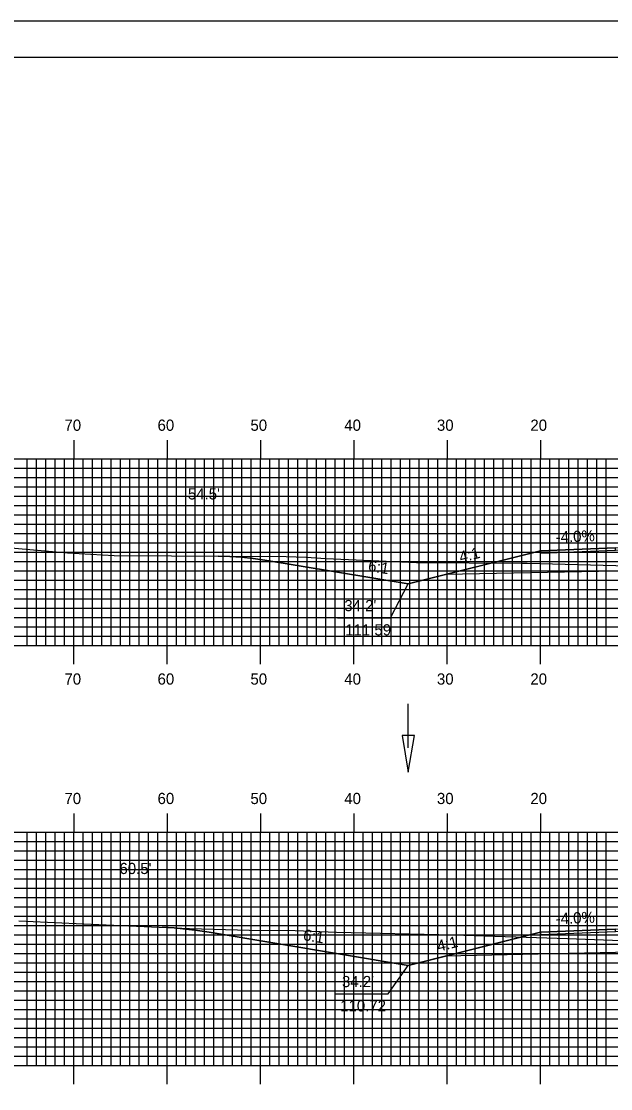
# Model space of a CAD drawing. Extents: x 1779893 to 1780236, y 442591 to 442811.
# Drawn here: x 1779982.7 to 1780045.9, y 442696.2 to 442810.5 of the extents above; entities that cross this region are included whole.
import ezdxf

# ---------------------------------------------------------------- set-up
doc = ezdxf.new("R2010")
doc.units = 0
for name, color, linetype in [('ANNOTATION', 7, 'Continuous'), ('BORDER', 7, 'Continuous'), ('D_Drainage_Ditch_Line', 7, 'Continuous'), ('D_Roadway_Centerline', 7, 'Continuous'), ('D_Roadway_Edge_Shoulder', 7, 'Continuous'), ('D_Roadway_SlopeLines', 7, 'Continuous'), ('D_Roadway_SubGrade', 7, 'Continuous'), ('D_Text_Standard', 7, 'Continuous'), ('H_V ANNOTATION', 7, 'Continuous'), ('MAJOR', 7, 'Continuous'), ('MINOR', 7, 'Continuous'), ('PLOT BOUNDARY', 7, 'Continuous'), ('S_Roadway_Centerline', 7, 'Continuous')]:
    doc.layers.add(name, color=color, linetype=linetype)

msp = doc.modelspace()

# ---------------------------------------------------------------- linework, layer by layer
at = {"layer": 'ANNOTATION'}
for points in [[(1780016.6, 442746.61), (1780022.29, 442746.61), (1780024.18, 442750.26)], [(1780016.34, 442706.32), (1780022.04, 442706.32), (1780024.18, 442709.38)]]:
    msp.add_lwpolyline(points, dxfattribs=at)
at = {"layer": 'BORDER'}
msp.add_lwpolyline([(1779908.76, 442596.67), (1780228.76, 442596.67), (1780228.76, 442806.67), (1779908.76, 442806.67)], close=True, dxfattribs=at)
at = {"layer": 'D_Drainage_Ditch_Line'}
msp.add_line((1780024.18, 442732.71), (1780024.18, 442737.41), dxfattribs=at)
msp.add_lwpolyline([(1780024.84, 442734.02), (1780023.53, 442734.02), (1780024.18, 442730.09)], close=True, dxfattribs=at)
at = {"layer": 'D_Roadway_Centerline'}
for points in [[(1780003.83, 442753.25), (1780005.08, 442753.21), (1780006.33, 442753.13), (1780007.58, 442753), (1780008.83, 442752.82), (1780024.18, 442750.26), (1780028.18, 442751.26), (1780038.36, 442753.8), (1780046.36, 442754.12), (1780058.36, 442754.36), (1780070.36, 442754.12), (1780078.36, 442753.8), (1780088.53, 442751.26), (1780092.53, 442750.26), (1780093.73, 442750.43), (1780094.94, 442750.53), (1780096.14, 442750.58), (1780097.34, 442750.56)], [(1779997.87, 442713.47), (1779999.12, 442713.39), (1780000.37, 442713.28), (1780001.62, 442713.12), (1780002.87, 442712.94), (1780024.18, 442709.38), (1780028.18, 442710.38), (1780038.36, 442712.93), (1780046.36, 442713.25), (1780058.36, 442713.49), (1780070.36, 442713.25), (1780078.36, 442712.93), (1780088.53, 442710.38), (1780092.53, 442709.38), (1780095.2, 442709.83), (1780096.45, 442710), (1780097.7, 442710.11), (1780098.95, 442710.16), (1780100.2, 442710.13)]]:
    msp.add_lwpolyline(points, dxfattribs=at)
at = {"layer": 'D_Roadway_Edge_Shoulder'}
for points in [[(1780046.36, 442754.12), (1780038.36, 442753.8), (1780038.36, 442753.55), (1780046.36, 442753.87)], [(1780046.36, 442713.25), (1780038.36, 442712.93), (1780038.36, 442712.68), (1780046.36, 442713)]]:
    msp.add_lwpolyline(points, close=True, dxfattribs=at)
at = {"layer": 'D_Roadway_SlopeLines'}
for points in [[(1780024.18, 442750.26), (1780008.83, 442752.82), (1780007.58, 442753), (1780006.33, 442753.13), (1780005.08, 442753.21), (1780003.83, 442753.25)], [(1780038.36, 442753.8), (1780024.18, 442750.26)], [(1780024.18, 442709.38), (1780002.87, 442712.94), (1780001.62, 442713.12), (1780000.37, 442713.28), (1779999.12, 442713.39), (1779997.87, 442713.47)], [(1780038.36, 442712.93), (1780024.18, 442709.38)]]:
    msp.add_lwpolyline(points, dxfattribs=at)
at = {"layer": 'D_Roadway_SubGrade'}
for points in [[(1780046.36, 442751.62), (1780028.18, 442751.26), (1780038.36, 442753.8), (1780038.36, 442753.55), (1780046.36, 442753.87), (1780058.36, 442754.11), (1780070.36, 442753.87), (1780078.36, 442753.55), (1780078.36, 442753.8), (1780088.53, 442751.26), (1780070.36, 442751.62), (1780058.36, 442751.86)], [(1780046.36, 442710.75), (1780028.18, 442710.38), (1780038.36, 442712.93), (1780038.36, 442712.68), (1780046.36, 442713), (1780058.36, 442713.24), (1780070.36, 442713), (1780078.36, 442712.68), (1780078.36, 442712.93), (1780088.53, 442710.38), (1780070.36, 442710.75), (1780058.36, 442710.99)]]:
    msp.add_lwpolyline(points, close=True, dxfattribs=at)
at = {"layer": 'MAJOR'}
for p, q in [((1779988.36, 442765.67), (1779988.36, 442763.67)), ((1779998.36, 442765.67), (1779998.36, 442763.67)), ((1780008.36, 442765.67), (1780008.36, 442763.67)), ((1780018.36, 442765.67), (1780018.36, 442763.67)), ((1780028.36, 442765.67), (1780028.36, 442763.67)), ((1780038.36, 442765.67), (1780038.36, 442763.67)), ((1779918.36, 442763.67), (1780198.36, 442763.67)), ((1779918.36, 442763.67), (1780198.36, 442763.67)), ((1779988.36, 442743.67), (1779988.36, 442763.67)), ((1779998.36, 442743.67), (1779998.36, 442763.67)), ((1780008.36, 442743.67), (1780008.36, 442763.67)), ((1780018.36, 442743.67), (1780018.36, 442763.67)), ((1780028.36, 442743.67), (1780028.36, 442763.67)), ((1780038.36, 442743.67), (1780038.36, 442763.67)), ((1779918.36, 442758.67), (1780198.36, 442758.67)), ((1779918.36, 442753.67), (1780198.36, 442753.67)), ((1779918.36, 442748.67), (1780198.36, 442748.67)), ((1779918.36, 442743.67), (1780198.36, 442743.67)), ((1779918.36, 442743.67), (1780198.36, 442743.67)), ((1779988.36, 442741.66), (1779988.36, 442743.67)), ((1779998.36, 442741.66), (1779998.36, 442743.67)), ((1780008.36, 442741.66), (1780008.36, 442743.67)), ((1780018.36, 442741.66), (1780018.36, 442743.67)), ((1780028.36, 442741.66), (1780028.36, 442743.67)), ((1780038.36, 442741.66), (1780038.36, 442743.67)), ((1779988.36, 442725.67), (1779988.36, 442723.67)), ((1779998.36, 442725.67), (1779998.36, 442723.67)), ((1780008.36, 442725.67), (1780008.36, 442723.67)), ((1780018.36, 442725.67), (1780018.36, 442723.67)), ((1780028.36, 442725.67), (1780028.36, 442723.67)), ((1780038.36, 442725.67), (1780038.36, 442723.67)), ((1779918.36, 442723.67), (1780198.36, 442723.67)), ((1779918.36, 442723.67), (1780198.36, 442723.67)), ((1779988.36, 442698.67), (1779988.36, 442723.67)), ((1779998.36, 442698.67), (1779998.36, 442723.67)), ((1780008.36, 442698.67), (1780008.36, 442723.67)), ((1780018.36, 442698.67), (1780018.36, 442723.67)), ((1780028.36, 442698.67), (1780028.36, 442723.67)), ((1780038.36, 442698.67), (1780038.36, 442723.67)), ((1779918.36, 442718.67), (1780198.36, 442718.67)), ((1779918.36, 442713.67), (1780198.36, 442713.67)), ((1779918.36, 442708.67), (1780198.36, 442708.67)), ((1779918.36, 442703.67), (1780198.36, 442703.67)), ((1779918.36, 442698.67), (1780198.36, 442698.67)), ((1779918.36, 442698.67), (1780198.36, 442698.67)), ((1779988.36, 442696.66), (1779988.36, 442698.67)), ((1779998.36, 442696.66), (1779998.36, 442698.67)), ((1780008.36, 442696.66), (1780008.36, 442698.67)), ((1780018.36, 442696.66), (1780018.36, 442698.67)), ((1780028.36, 442696.66), (1780028.36, 442698.67)), ((1780038.36, 442696.66), (1780038.36, 442698.67))]:
    msp.add_line(p, q, dxfattribs=at)
at = {"layer": 'MINOR'}
for p, q in [((1779983.36, 442743.67), (1779983.36, 442763.67)), ((1779984.36, 442743.67), (1779984.36, 442763.67)), ((1779985.36, 442743.67), (1779985.36, 442763.67)), ((1779986.36, 442743.67), (1779986.36, 442763.67)), ((1779987.36, 442743.67), (1779987.36, 442763.67)), ((1779989.36, 442743.67), (1779989.36, 442763.67)), ((1779990.36, 442743.67), (1779990.36, 442763.67)), ((1779991.36, 442743.67), (1779991.36, 442763.67)), ((1779992.36, 442743.67), (1779992.36, 442763.67)), ((1779993.36, 442743.67), (1779993.36, 442763.67)), ((1779994.36, 442743.67), (1779994.36, 442763.67)), ((1779995.36, 442743.67), (1779995.36, 442763.67)), ((1779996.36, 442743.67), (1779996.36, 442763.67)), ((1779997.36, 442743.67), (1779997.36, 442763.67)), ((1779999.36, 442743.67), (1779999.36, 442763.67)), ((1780000.36, 442743.67), (1780000.36, 442763.67)), ((1780001.36, 442743.67), (1780001.36, 442763.67)), ((1780002.36, 442743.67), (1780002.36, 442763.67)), ((1780003.36, 442743.67), (1780003.36, 442763.67)), ((1780004.36, 442743.67), (1780004.36, 442763.67)), ((1780005.36, 442743.67), (1780005.36, 442763.67)), ((1780006.36, 442743.67), (1780006.36, 442763.67)), ((1780007.36, 442743.67), (1780007.36, 442763.67)), ((1780009.36, 442743.67), (1780009.36, 442763.67)), ((1780010.36, 442743.67), (1780010.36, 442763.67)), ((1780011.36, 442743.67), (1780011.36, 442763.67)), ((1780012.36, 442743.67), (1780012.36, 442763.67)), ((1780013.36, 442743.67), (1780013.36, 442763.67)), ((1780014.36, 442743.67), (1780014.36, 442763.67)), ((1780015.36, 442743.67), (1780015.36, 442763.67)), ((1780016.36, 442743.67), (1780016.36, 442763.67)), ((1780017.36, 442743.67), (1780017.36, 442763.67)), ((1780019.36, 442743.67), (1780019.36, 442763.67)), ((1780020.36, 442743.67), (1780020.36, 442763.67)), ((1780021.36, 442743.67), (1780021.36, 442763.67)), ((1780022.36, 442743.67), (1780022.36, 442763.67)), ((1780023.36, 442743.67), (1780023.36, 442763.67)), ((1780024.36, 442743.67), (1780024.36, 442763.67)), ((1780025.36, 442743.67), (1780025.36, 442763.67)), ((1780026.36, 442743.67), (1780026.36, 442763.67)), ((1780027.36, 442743.67), (1780027.36, 442763.67)), ((1780029.36, 442743.67), (1780029.36, 442763.67)), ((1780030.36, 442743.67), (1780030.36, 442763.67)), ((1780031.36, 442743.67), (1780031.36, 442763.67)), ((1780032.36, 442743.67), (1780032.36, 442763.67)), ((1780033.36, 442743.67), (1780033.36, 442763.67)), ((1780034.36, 442743.67), (1780034.36, 442763.67)), ((1780035.36, 442743.67), (1780035.36, 442763.67)), ((1780036.36, 442743.67), (1780036.36, 442763.67)), ((1780037.36, 442743.67), (1780037.36, 442763.67)), ((1780039.36, 442743.67), (1780039.36, 442763.67)), ((1780040.36, 442743.67), (1780040.36, 442763.67)), ((1780041.36, 442743.67), (1780041.36, 442763.67)), ((1780042.36, 442743.67), (1780042.36, 442763.67)), ((1780043.36, 442743.67), (1780043.36, 442763.67)), ((1780044.36, 442743.67), (1780044.36, 442763.67)), ((1780045.36, 442743.67), (1780045.36, 442763.67)), ((1779918.36, 442762.67), (1780198.36, 442762.67)), ((1779918.36, 442761.67), (1780198.36, 442761.67)), ((1779918.36, 442760.67), (1780198.36, 442760.67)), ((1779918.36, 442759.67), (1780198.36, 442759.67)), ((1779918.36, 442757.67), (1780198.36, 442757.67)), ((1779918.36, 442756.67), (1780198.36, 442756.67)), ((1779918.36, 442755.67), (1780198.36, 442755.67)), ((1779918.36, 442754.67), (1780198.36, 442754.67)), ((1779918.36, 442752.67), (1780198.36, 442752.67)), ((1779918.36, 442751.67), (1780198.36, 442751.67)), ((1779918.36, 442750.67), (1780198.36, 442750.67)), ((1779918.36, 442749.67), (1780198.36, 442749.67)), ((1779918.36, 442747.67), (1780198.36, 442747.67)), ((1779918.36, 442746.67), (1780198.36, 442746.67)), ((1779918.36, 442745.67), (1780198.36, 442745.67)), ((1779918.36, 442744.67), (1780198.36, 442744.67)), ((1779983.36, 442698.67), (1779983.36, 442723.67)), ((1779984.36, 442698.67), (1779984.36, 442723.67)), ((1779985.36, 442698.67), (1779985.36, 442723.67)), ((1779986.36, 442698.67), (1779986.36, 442723.67)), ((1779987.36, 442698.67), (1779987.36, 442723.67)), ((1779989.36, 442698.67), (1779989.36, 442723.67)), ((1779990.36, 442698.67), (1779990.36, 442723.67)), ((1779991.36, 442698.67), (1779991.36, 442723.67)), ((1779992.36, 442698.67), (1779992.36, 442723.67)), ((1779993.36, 442698.67), (1779993.36, 442723.67)), ((1779994.36, 442698.67), (1779994.36, 442723.67)), ((1779995.36, 442698.67), (1779995.36, 442723.67)), ((1779996.36, 442698.67), (1779996.36, 442723.67)), ((1779997.36, 442698.67), (1779997.36, 442723.67)), ((1779999.36, 442698.67), (1779999.36, 442723.67)), ((1780000.36, 442698.67), (1780000.36, 442723.67)), ((1780001.36, 442698.67), (1780001.36, 442723.67)), ((1780002.36, 442698.67), (1780002.36, 442723.67)), ((1780003.36, 442698.67), (1780003.36, 442723.67)), ((1780004.36, 442698.67), (1780004.36, 442723.67)), ((1780005.36, 442698.67), (1780005.36, 442723.67)), ((1780006.36, 442698.67), (1780006.36, 442723.67)), ((1780007.36, 442698.67), (1780007.36, 442723.67)), ((1780009.36, 442698.67), (1780009.36, 442723.67)), ((1780010.36, 442698.67), (1780010.36, 442723.67)), ((1780011.36, 442698.67), (1780011.36, 442723.67)), ((1780012.36, 442698.67), (1780012.36, 442723.67)), ((1780013.36, 442698.67), (1780013.36, 442723.67)), ((1780014.36, 442698.67), (1780014.36, 442723.67)), ((1780015.36, 442698.67), (1780015.36, 442723.67)), ((1780016.36, 442698.67), (1780016.36, 442723.67)), ((1780017.36, 442698.67), (1780017.36, 442723.67)), ((1780019.36, 442698.67), (1780019.36, 442723.67)), ((1780020.36, 442698.67), (1780020.36, 442723.67)), ((1780021.36, 442698.67), (1780021.36, 442723.67)), ((1780022.36, 442698.67), (1780022.36, 442723.67)), ((1780023.36, 442698.67), (1780023.36, 442723.67)), ((1780024.36, 442698.67), (1780024.36, 442723.67)), ((1780025.36, 442698.67), (1780025.36, 442723.67)), ((1780026.36, 442698.67), (1780026.36, 442723.67)), ((1780027.36, 442698.67), (1780027.36, 442723.67)), ((1780029.36, 442698.67), (1780029.36, 442723.67)), ((1780030.36, 442698.67), (1780030.36, 442723.67)), ((1780031.36, 442698.67), (1780031.36, 442723.67)), ((1780032.36, 442698.67), (1780032.36, 442723.67)), ((1780033.36, 442698.67), (1780033.36, 442723.67)), ((1780034.36, 442698.67), (1780034.36, 442723.67)), ((1780035.36, 442698.67), (1780035.36, 442723.67)), ((1780036.36, 442698.67), (1780036.36, 442723.67)), ((1780037.36, 442698.67), (1780037.36, 442723.67)), ((1780039.36, 442698.67), (1780039.36, 442723.67)), ((1780040.36, 442698.67), (1780040.36, 442723.67)), ((1780041.36, 442698.67), (1780041.36, 442723.67)), ((1780042.36, 442698.67), (1780042.36, 442723.67)), ((1780043.36, 442698.67), (1780043.36, 442723.67)), ((1780044.36, 442698.67), (1780044.36, 442723.67)), ((1780045.36, 442698.67), (1780045.36, 442723.67)), ((1779918.36, 442722.67), (1780198.36, 442722.67)), ((1779918.36, 442721.67), (1780198.36, 442721.67)), ((1779918.36, 442720.67), (1780198.36, 442720.67)), ((1779918.36, 442719.67), (1780198.36, 442719.67)), ((1779918.36, 442717.67), (1780198.36, 442717.67)), ((1779918.36, 442716.67), (1780198.36, 442716.67)), ((1779918.36, 442715.67), (1780198.36, 442715.67)), ((1779918.36, 442714.67), (1780198.36, 442714.67)), ((1779918.36, 442712.67), (1780198.36, 442712.67)), ((1779918.36, 442711.67), (1780198.36, 442711.67)), ((1779918.36, 442710.67), (1780198.36, 442710.67)), ((1779918.36, 442709.67), (1780198.36, 442709.67)), ((1779918.36, 442707.67), (1780198.36, 442707.67)), ((1779918.36, 442706.67), (1780198.36, 442706.67)), ((1779918.36, 442705.67), (1780198.36, 442705.67)), ((1779918.36, 442704.67), (1780198.36, 442704.67)), ((1779918.36, 442702.67), (1780198.36, 442702.67)), ((1779918.36, 442701.67), (1780198.36, 442701.67)), ((1779918.36, 442700.67), (1780198.36, 442700.67)), ((1779918.36, 442699.67), (1780198.36, 442699.67))]:
    msp.add_line(p, q, dxfattribs=at)
at = {"layer": 'PLOT BOUNDARY'}
msp.add_lwpolyline([(1779892.57, 442590.55), (1780232.57, 442590.55), (1780232.57, 442810.55), (1779892.57, 442810.55)], close=True, dxfattribs=at)
at = {"layer": 'S_Roadway_Centerline'}
for points in [[(1779978.36, 442754.4), (1779987.69, 442753.59), (1779992.67, 442753.3), (1780011.12, 442753.21), (1780013.23, 442753.13), (1780015.36, 442753), (1780025.08, 442752.55), (1780036.36, 442752.49), (1780036.9, 442752.48), (1780058.61, 442751.92), (1780059.28, 442751.91), (1780059.98, 442751.86), (1780081.24, 442750.87), (1780081.37, 442750.86), (1780094.18, 442750.69), (1780105.77, 442750.19), (1780105.91, 442750.19), (1780116.83, 442750.05), (1780128.02, 442749.91)], [(1779982.49, 442714.17), (1779988.63, 442713.86), (1779995.07, 442713.6), (1780000.76, 442713.33), (1780007.19, 442713.15), (1780012.06, 442713.11), (1780016.48, 442712.94), (1780029.01, 442712.66), (1780041.25, 442712.26), (1780047.02, 442712.04), (1780053.26, 442711.88), (1780062.8, 442711.56), (1780069.73, 442711.28), (1780076.94, 442710.98), (1780081.15, 442710.87), (1780085.17, 442710.66), (1780092.85, 442710.47), (1780101.05, 442710.09), (1780108.34, 442709.83), (1780126.08, 442709.42)]]:
    msp.add_lwpolyline(points, dxfattribs=at)

# ---------------------------------------------------------------- texts
at = {"layer": 'ANNOTATION'}
for s, rotation, p in [('-4.0%', 2.2906, (1780039.99, 442754.67)), ('4:1', 14.0362, (1780029.8, 442752.53)), ('6:1', 350.5377, (1780019.82, 442751.66)), ('-4.0%', 2.2906, (1780039.99, 442713.79)), ('6:1', 350.5377, (1780012.86, 442712.1)), ('4:1', 14.0362, (1780027.43, 442710.84))]:
    msp.add_text(s, height=1.2, rotation=rotation, dxfattribs=at).set_placement(p)
for s, p in [("34.2'", (1780017.33, 442747.34)), ('111.59', (1780017.43, 442744.74)), ("34.2'", (1780017.08, 442707.05)), ('110.72', (1780016.89, 442704.45))]:
    msp.add_text(s, height=1.2, dxfattribs=at).set_placement(p)
at = {"layer": 'D_Text_Standard'}
for s, p in [("54.5'", (1780000.58, 442759.31)), ("60.5'", (1779993.25, 442719.17))]:
    msp.add_text(s, height=1.2, dxfattribs=at).set_placement(p)
at = {"layer": 'H_V ANNOTATION'}
for s, p in [('70', (1779987.36, 442766.67)), ('60', (1779997.33, 442766.67)), ('50', (1780007.28, 442766.67)), ('40', (1780017.33, 442766.67)), ('30', (1780027.25, 442766.67)), ('20', (1780037.26, 442766.67)), ('70', (1779987.36, 442739.47)), ('60', (1779997.33, 442739.47)), ('50', (1780007.28, 442739.47)), ('40', (1780017.33, 442739.47)), ('30', (1780027.25, 442739.47)), ('20', (1780037.26, 442739.47)), ('70', (1779987.36, 442726.67)), ('60', (1779997.33, 442726.67)), ('50', (1780007.28, 442726.67)), ('40', (1780017.33, 442726.67)), ('30', (1780027.25, 442726.67)), ('20', (1780037.26, 442726.67))]:
    msp.add_text(s, height=1.2, dxfattribs=at).set_placement(p)

doc.saveas('drawing.dxf')
